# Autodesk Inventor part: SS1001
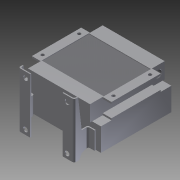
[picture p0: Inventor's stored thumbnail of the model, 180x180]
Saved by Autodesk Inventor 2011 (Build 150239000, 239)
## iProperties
Created: 2011-08
Part Number: SS1001
Document SubType Name: Modeling
Designer: khramov
Density: 1 g/cm^3
Author: khramov
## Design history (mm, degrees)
sketch "Эскиз1"
  geometry: L1 (0, 0)-(226, 0); L2 (226, 0)-(226, -200); L3 (226, -200)-(0, -200); L4 (0, -200)-(0, 0)
  constraints: 8 end point, 2 parallel, 1 horizontal, 1 perpendicular
  dimensions: "d0" = 226 distance of L1.start L1.end; "d1" = 200 distance of L3.end L1.start
extrude "Выдавливание1" new body sketch "Эскиз1" distance "d2" = 65; taper "d3" = 0 deg
sketch "Эскиз2"
  geometry: L1 (0, 0)-(-226, 0) reference; L2 (-226, 0)-(-226, -200) reference; L3 (-226, -200)-(0, -200) reference; L4 (0, -200)-(0, 0) reference; L5 (-226, -100)-(0, -100); L6 (-113, 0)-(-113, -200); C1 r 85 at (-113, -100)
  constraints: 5 midpoint, 4 end point, 1 centre point
  dimensions: "d4" = 170 diameter of C1
extrude "Выдавливание2" join sketch "Эскиз2" distance "d5" = 15; taper "d6" = 0 deg
sketch "Эскиз3"
  geometry: L1 (226, -200)-(0, -200) reference; L2 (0, -206)-(226, -206); L3 (226, -206)-(226, 6); L4 (226, 6)-(0, 6); L5 (0, 6)-(0, -206)
  constraints: 8 end point, 2 parallel, 1 horizontal, 1 perpendicular
  dimensions: "d7" = 212 distance of L4.end L2.start; "d8" = 6 distance between parallel lines of L2 L1
extrude "Выдавливание3" join sketch "Эскиз3" distance "d9" = 45; taper "d10" = 0 deg
sketch "Эскиз4"
  geometry: L1 (0, -45)-(226, -45) reference; L2 (0, 0)-(0, -45) reference; L3 (0, -40)-(25, -40); L4 (25, -40)-(25, -5); L5 (25, -5)-(0, -5); L6 (0, -5)-(0, -40); L7 (113, -45)-(113, 159.322); L8 (201, -40)-(201, -5); L9 (226, -40)-(201, -40); L10 (201, -5)-(226, -5); L11 (226, -5)-(226, -40); 1 further point
  constraints: 18 end point, 4 symmetric about line, 3 parallel, 1 horizontal, 1 midpoint, 1 perpendicular, 1 point on line
  dimensions: "d11" = 35 distance of L3.end L4.end; "d12" = 5 distance between parallel lines of L3 L1; "d13" = 25 distance of L3.start L3.end
extrude "Выдавливание4" cut sketch "Эскиз4" stored distance "d14" = 45; taper "d15" = 0 deg
sketch "Эскиз5"
  geometry: L1 (0, 6)-(25, 6); L2 (25, 6)-(25, -30); L3 (25, -30)-(0, -30); L4 (0, -30)-(0, 6); L5 (0, -206)-(25, -206); L6 (25, -206)-(25, -170); L7 (25, -170)-(0, -170); L8 (0, -170)-(0, -206); L9 (0, 6)-(226, 6) reference; L10 (113, 6)-(113, -206); L11 (0, -206)-(226, -206) reference; L12 (226, 6)-(201, 6); L13 (201, 6)-(201, -30); L14 (201, -30)-(226, -30); L15 (226, -30)-(226, 6); L16 (226, -206)-(201, -206); L17 (201, -206)-(201, -170); L18 (201, -170)-(226, -170); L19 (226, -170)-(226, -206); 2 further points
  constraints: 34 end point, 7 symmetric about line, 4 parallel, 2 horizontal, 2 midpoint, 2 perpendicular
  dimensions: "d16" = 36 distance of L1.end L2.end; "d17" = 36 distance of L5.end L6.end; "d18" = 140 distance between parallel lines of L3 L7 (derived); "d19" = 25 distance of L6.end L7.end; "d20" = 25 distance of L2.end L3.end
extrude "Выдавливание6" cut sketch "Эскиз5" distance "d23" = 45; taper "d24" = 0 deg
sketch "Эскиз6"
  geometry: L1 (25, -30)-(0, -30) reference; L2 (12.5, -48)-(213.5, -48); L3 (213.5, -48)-(213.5, -152); L4 (213.5, -152)-(12.5, -152); L5 (12.5, -152)-(12.5, -48); L6 (12.5, -100)-(213.5, -100); C1 r 4.5 at (12.5, -48); C2 r 4.5 at (213.5, -48); C3 r 4.5 at (213.5, -152); C4 r 4.5 at (12.5, -152); 2 further points
  constraints: 10 end point, 4 centre point, 4 coincident, 2 midpoint, 2 parallel, 1 horizontal, 1 perpendicular
  dimensions: "d25" = 201 distance of L2.start L2.end; "d26" = 104 distance of L4.end L2.start; "d27" = 140 distance of point (0, -170) L1.end (derived); "d28" = 70 distance between parallel lines of L6 L1; "d29" = 9 diameter of C1; "d30" = 9 diameter of C2; "d31" = 9 diameter of C3; "d32" = 9 diameter of C4
extrude "Выдавливание7" cut sketch "Эскиз6" stored distance "d33" = 45; taper "d34" = 0 deg
sketch "Эскиз7"
  geometry: L1 (25, -30)-(0, -30) reference; L2 (0, -170)-(25, -170) reference; L3 (25, -30)-(25, -170) reference; L4 (201, -30)-(201, -170) reference; L5 (25, -33)-(201, -33); L6 (201, -33)-(201, -167); L7 (201, -167)-(25, -167); L8 (25, -167)-(25, -33); 1 further point
  constraints: 8 end point, 2 parallel, 2 point on line, 1 horizontal, 1 perpendicular
  dimensions: "d35" = 3 distance between parallel lines of L5 L1; "d36" = 3 distance between parallel lines of L2 L7
extrude "Выдавливание8" cut sketch "Эскиз7" distance "d37" = 2; taper "d38" = 0 deg
sketch "Эскиз8"
  geometry: L1 (226, -200)-(201, -200) reference; L2 (210.927, -200)-(210.927, -203); L3 (201, -206)-(201, -170) reference; L4 (210.927, -203)-(197, -203); L5 (192, -208)-(192, -237); L6 (187, -242)-(159, -242); L7 (159, -242)-(159, -239); L8 (159, -239)-(184, -239); L9 (189, -234)-(189, -205); L10 (201, -206)-(25, -206) reference; L11 (194, -200)-(210.927, -200); L12 (113, -100)-(113, -313.956); L13 (25, 0)-(201, 0) reference; L14 (172, -229.595)-(172, -261.848); L15 (226, -200)-(0, -200) reference; L16 (15.073, -200)-(15.073, -203); L17 (15.073, -203)-(29, -203); L18 (32, -200)-(15.073, -200); L19 (67, -239)-(42, -239); L20 (37, -234)-(37, -205); L21 (34, -208)-(34, -237); L22 (39, -242)-(67, -242); L23 (67, -242)-(67, -239); L24 (54, -229.595)-(54, -261.848); C1 r 85 at (113, -100) reference; A1 r 5 centre (187, -237) between (187, -242) and (192, -237); A2 r 5 centre (184, -234) between (184, -239) and (189, -234); A3 r 5 centre (197, -208) between (197, -203) and (192, -208); A4 r 5 centre (194, -205) between (194, -200) and (189, -205); A5 r 5 centre (32, -205) between (37, -205) and (32, -200); A6 r 5 centre (29, -208) between (34, -208) and (29, -203); A7 r 5 centre (42, -234) between (37, -234) and (42, -239); A8 r 5 centre (39, -237) between (34, -237) and (39, -242); 2 further points
  constraints: 38 end point, 19 symmetric about line, 16 point on circle, 8 centre point, 8 tangent, 5 parallel, 4 perpendicular, 3 equal radius, 1 collinear, 1 point on line, 4 other
  dimensions: "d39" = 3 distance of L6.end L7.end; "d40" = 3 distance between parallel lines of L5 L9; "d41" = 3 distance of L2.start L2.end; "d42" = 13 distance from line of L7 L14.start; "d43" = 17 distance from line of L9 L14.start; "d44" = 42 distance between parallel lines of L6 L15; "d45" = 5 radius of A1; "d47" = 59 distance between parallel lines of L12 L14; "d48" = 118 distance between parallel lines of L24 L14 (derived)
extrude "Выдавливание9" join sketch "Эскиз8" distance "d49" = 70; taper "d51" = 0 deg; dims "d50" = 86, "d52" = 0
sketch "Эскиз9"
  geometry: L1 (0, -27.593)-(85.973, -17.473); L2 (85.973, -17.473)-(85.973, 3); L3 (0, 3)-(0, -27.593); L4 (0, 3)-(85.973, 3); L5 (135, 3)-(141.986, -17.473); L6 (141.986, -17.473)-(156, -24.718); L7 (156, -24.718)-(156, 3); L8 (156, 3)-(135, 3) reference; L9 (156, 3)-(135, 3); 1 further point
  constraints: 16 end point, 2 perpendicular
extrude "Выдавливание10" cut sketch "Эскиз9" distance "d53" = 500; taper "d54" = 0 deg
sketch "Эскиз10"
  geometry: L1 (13, -16.5)-(-105, -16.5); L2 (-105, -16.5)-(-105, -142.5); L3 (-105, -142.5)-(13, -142.5); L4 (13, -142.5)-(13, -16.5); L5 (-134, -25)-(42, -25) reference; L6 (39, -150)-(-131, -150) reference; L7 (-46, -150)-(-46, -269.723); C1 r 6.5 at (13, -16.5); C2 r 6.5 at (13, -142.5); C3 r 6.5 at (-105, -142.5); C4 r 6.5 at (-105, -16.5); 1 further point
  constraints: 10 end point, 4 centre point, 4 coincident, 2 parallel, 2 perpendicular, 1 horizontal, 1 midpoint
  dimensions: "d55" = 13 diameter of C1; "d56" = 13 diameter of C2; "d57" = 13 diameter of C3; "d58" = 13 diameter of C4; "d59" = 126 distance of L3.end L1.start; "d60" = 118 distance of L1.start L1.end; "d61" = 8.5 distance from line of C1.centre L5; "d63" = 59 distance between parallel lines of L2 L7
extrude "Выдавливание11" cut sketch "Эскиз10" distance "d64" = 10; taper "d65" = 0 deg
sketch "Эскиз11"
  geometry: L1 (0, 0)-(45, 0) reference; L2 (22.5, 0)-(22.5, -18); L3 (40, -36)-(45, -36) reference; 2 further points
  constraints: 2 end point, 1 coincident, 1 midpoint, 1 perpendicular
  dimensions: "d66" = 18 distance from line of point (22.5, -18) L1
hole "Отверстие1" sketch "Эскиз11" at (22.5, -18) diameter "d67" = 18.631; stored, may be unused: countersink angle "d71" = 90 deg, drill point angle "d73" = 118 deg; dims "d68" = 25, "d69" = 21, "d70" = 2, "d72" = 30
sketch "Эскиз12"
  geometry: L1 (45, -176)-(40, -176) reference; L2 (0, -206)-(45, -206); L3 (45, -206)-(45, -212); L4 (45, -212)-(0, -212); L5 (0, -212)-(0, -206); 1 further point
  constraints: 8 end point, 2 parallel, 1 horizontal, 1 perpendicular
  dimensions: "d74" = 36 distance between parallel lines of L1 L4
extrude "Выдавливание13" join sketch "Эскиз12" distance "d77" = 176; taper "d78" = 0 deg
sketch "Эскиз13"
  geometry: L1 (0, -212)-(45, -212) reference; L2 (22.5, -212)-(22.5, -194); 2 further points
  constraints: 2 end point, 1 coincident, 1 midpoint, 1 perpendicular
  dimensions: "d79" = 18 distance of L2.start L2.end
hole "Отверстие2" sketch "Эскиз13" at (22.5, -194) diameter "d80" = 18.631; stored, may be unused: countersink angle "d84" = 90 deg, drill point angle "d86" = 118 deg; dims "d81" = 25, "d82" = 21, "d83" = 2, "d85" = 30
sketch "Эскиз17"
  geometry: L1 (20.229, -167.513)-(38.2, -167.513); L2 (38.2, -167.513)-(38.2, -177.227); L3 (38.2, -177.227)-(20.229, -177.227); L4 (20.229, -177.227)-(20.229, -167.513); 1 further point
  constraints: 2 other
extrude "Выдавливание16" cut sketch "Эскиз17" distance "d97" = 1; taper "d98" = 0 deg
sketch "Эскиз18"
  geometry: L1 (17.579, -38.459)-(33.232, -38.459); L2 (33.232, -38.459)-(33.232, -46.439); L3 (33.232, -46.439)-(17.579, -46.439); L4 (17.579, -46.439)-(17.579, -38.459); 1 further point
  constraints: 2 other
extrude "Выдавливание17" cut sketch "Эскиз18" distance "d99" = 1; taper "d100" = 0 deg
node "Твердое тело1"
